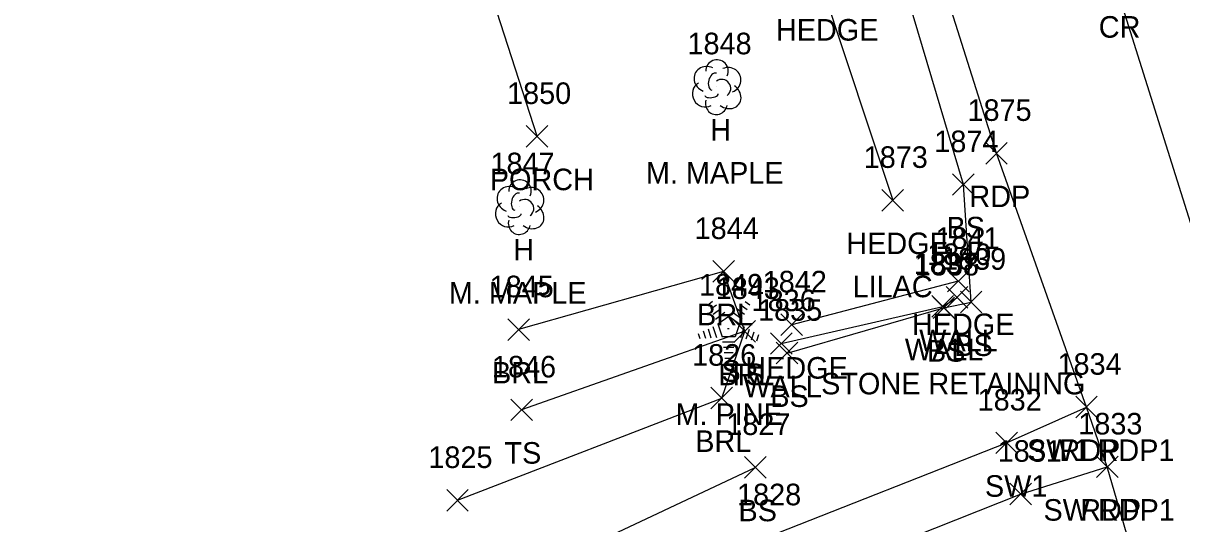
# Model space of a CAD drawing. Extents: x 1620157 to 1620595, y 115111 to 117885.
# Drawn here: x 1620193.4 to 1620300.9, y 115501.6 to 115548.1 of the extents above; entities that cross this region are included whole.
import ezdxf

# ---------------------------------------------------------------- set-up
doc = ezdxf.new("R2010")
doc.units = 0
for name, color, linetype in [('L_A', 7, 'Continuous'), ('L_C', 7, 'Continuous'), ('L_I', 7, 'Continuous'), ('L_TIC', 7, 'Continuous'), ('LABL', 7, 'Continuous'), ('LAHR', 7, 'Continuous'), ('LBF', 7, 'Continuous'), ('LELB', 7, 'Continuous'), ('LTC', 7, 'Continuous'), ('LTD', 7, 'Continuous'), ('LW', 7, 'Continuous'), ('P_A', 7, 'Continuous'), ('P_I', 7, 'Continuous'), ('P_TIC', 7, 'Continuous'), ('PET', 7, 'Continuous'), ('PRC', 7, 'Continuous'), ('R_A', 7, 'Continuous'), ('R_I', 7, 'Continuous'), ('R_TIC', 7, 'Continuous'), ('RSW', 7, 'Continuous')]:
    doc.layers.add(name, color=color, linetype=linetype)

msp = doc.modelspace()

# ---------------------------------------------------------------- linework, layer by layer
at = {"layer": 'L_TIC'}
for points in [[(1620240.04, 115536.59), (1620242.04, 115538.59)], [(1620242.04, 115536.59), (1620240.04, 115538.59)], [(1620279.6, 115532.12), (1620281.6, 115534.12)], [(1620281.6, 115532.12), (1620279.6, 115534.12)], [(1620273.04, 115530.66), (1620275.04, 115532.66)], [(1620275.04, 115530.66), (1620273.04, 115532.66)], [(1620257.35, 115524.06), (1620259.35, 115526.06)], [(1620259.35, 115524.06), (1620257.35, 115526.06)], [(1620279.13, 115523.15), (1620281.13, 115525.15)], [(1620281.13, 115523.15), (1620279.13, 115525.15)], [(1620279.01, 115521.65), (1620281.01, 115523.65)], [(1620281.01, 115521.65), (1620279.01, 115523.65)], [(1620280.32, 115521.21), (1620282.32, 115523.21)], [(1620282.32, 115521.21), (1620280.32, 115523.21)], [(1620277.68, 115520.81), (1620279.68, 115522.81)], [(1620279.68, 115520.81), (1620277.68, 115522.81)], [(1620277.78, 115520.68), (1620279.78, 115522.68)], [(1620279.78, 115520.68), (1620277.78, 115522.68)], [(1620263.67, 115519.11), (1620265.67, 115521.11)], [(1620265.67, 115519.11), (1620263.67, 115521.11)], [(1620238.33, 115518.66), (1620240.33, 115520.66)], [(1620240.33, 115518.66), (1620238.33, 115520.66)], [(1620259.32, 115518.5), (1620261.32, 115520.5)], [(1620261.32, 115518.5), (1620259.32, 115520.5)], [(1620259.32, 115518.5), (1620261.32, 115520.5)], [(1620261.32, 115518.5), (1620259.32, 115520.5)], [(1620262.7, 115517.37), (1620264.7, 115519.37)], [(1620264.7, 115517.37), (1620262.7, 115519.37)], [(1620263.24, 115516.48), (1620265.24, 115518.48)], [(1620265.24, 115516.48), (1620263.24, 115518.48)], [(1620257.18, 115512.31), (1620259.18, 115514.31)], [(1620259.18, 115512.31), (1620257.18, 115514.31)], [(1620238.61, 115511.22), (1620240.61, 115513.22)], [(1620240.61, 115511.22), (1620238.61, 115513.22)], [(1620260.29, 115505.88), (1620262.29, 115507.88)], [(1620262.29, 115505.88), (1620260.29, 115507.88)], [(1620232.66, 115502.82), (1620234.66, 115504.82)], [(1620234.66, 115502.82), (1620232.66, 115504.82)]]:
    msp.add_lwpolyline(points, dxfattribs=at)
at = {"layer": 'LABL'}
msp.add_lwpolyline([(1620233.66, 115503.82), (1620258.18, 115513.31), (1620260.32, 115519.5), (1620258.35, 115525.06), (1620239.33, 115519.66)], dxfattribs=at)
at = {"layer": 'LAHR'}
for points in [[(1620267.51, 115551.47), (1620274.04, 115531.66)], [(1620280.13, 115524.15), (1620264.67, 115520.11)]]:
    msp.add_lwpolyline(points, dxfattribs=at)
at = {"layer": 'LBF'}
msp.add_lwpolyline([(1620241.04, 115537.59), (1620235.29, 115555.41), (1620233.08, 115561.87), (1620232.99, 115562.77)], dxfattribs=at)
at = {"layer": 'LELB'}
for points in [[(1620264.24, 115517.48), (1620278.78, 115521.68), (1620281.32, 115522.21), (1620280.6, 115533.12), (1620271.27, 115564.52), (1620264.78, 115582.86), (1620240.11, 115585.85)], [(1620260.32, 115519.5), (1620239.61, 115512.22)], [(1620235.85, 115494.91), (1620261.29, 115506.88)]]:
    msp.add_lwpolyline(points, dxfattribs=at)
at = {"layer": 'LTC'}
for p, q in [((1620256.97, 115522.03), (1620257.32, 115522.29)), ((1620257.18, 115521.57), (1620257.7, 115521.95)), ((1620259.99, 115521.92), (1620260.54, 115521.52)), ((1620260.36, 115522.27), (1620260.78, 115521.97)), ((1620257.39, 115521.1), (1620258.09, 115521.61)), ((1620257.59, 115520.63), (1620258.47, 115521.27)), ((1620257.82, 115520.18), (1620258.83, 115520.91)), ((1620258.83, 115520.91), (1620259.83, 115520.19)), ((1620259.25, 115521.23), (1620260.06, 115520.64)), ((1620259.62, 115521.57), (1620260.3, 115521.08)), ((1620257.36, 115519.96), (1620257.7, 115518.94)), ((1620257.82, 115520.18), (1620258.21, 115518.99)), ((1620259.83, 115520.19), (1620259.44, 115518.99)), ((1620260.27, 115519.92), (1620259.93, 115518.88)), ((1620256, 115519.31), (1620256.15, 115518.84)), ((1620256.45, 115519.53), (1620256.67, 115518.87)), ((1620256.91, 115519.74), (1620257.18, 115518.91)), ((1620259.44, 115518.99), (1620258.21, 115518.99)), ((1620260.71, 115519.67), (1620260.42, 115518.78)), ((1620261.15, 115519.42), (1620260.92, 115518.69)), ((1620261.6, 115519.17), (1620261.41, 115518.59)), ((1620259.4, 115518.49), (1620258.25, 115518.49)), ((1620259.31, 115517.99), (1620258.33, 115517.99)), ((1620259.23, 115517.49), (1620258.4, 115517.49)), ((1620259.15, 115516.99), (1620258.47, 115516.99))]:
    msp.add_line(p, q, dxfattribs=at)
at = {"layer": 'LTD'}
for p, q in [((1620257.69, 115542.2), (1620257.69, 115542.2)), ((1620257.69, 115542.2), (1620257.69, 115542.2)), ((1620239.41, 115531.07), (1620239.41, 115531.07)), ((1620239.41, 115531.07), (1620239.41, 115531.07))]:
    msp.add_line(p, q, dxfattribs=at)
for centre in [(1620257.74, 115543.64), (1620239.46, 115532.5)]:
    msp.add_arc(centre, 1.05, 335.5272, 180.9563, dxfattribs=at)
for centre, major_axis, ratio, start_param, end_param in [((1620256.9, 115542.87), (1.21, -0.51), 0.895232, 1.570796, 4.712389), ((1620257.48, 115542.66), (-0.208, -0.792), 0.645439, 3.141593, 6.283185), ((1620258.73, 115542.79), (-1.14, -0.48), 0.949671, 1.570796, 4.712389), ((1620256.61, 115541.49), (0.58, -1.04), 0.959034, 3.141593, 6.283185), ((1620258.19, 115542.04), (-0.5, 0.667), 0.989748, 3.141593, 6.283185), ((1620257.23, 115541.45), (-0.625, -0.083), 0.423636, 0, 3.141593), ((1620258.69, 115541.37), (-1.09, 0.79), 0.841452, 1.570796, 4.712389), ((1620257.69, 115540.7), (0.26, 1.06), 0.942809, 1.570796, 4.712389), ((1620238.62, 115531.73), (1.21, -0.51), 0.895232, 1.570796, 4.712389), ((1620240.45, 115531.65), (-1.14, -0.48), 0.949671, 1.570796, 4.712389), ((1620239.2, 115531.52), (-0.208, -0.792), 0.645439, 3.141593, 6.283185), ((1620239.91, 115530.9), (-0.5, 0.667), 0.989748, 3.141593, 6.283185), ((1620238.33, 115530.36), (0.58, -1.04), 0.959034, 3.141593, 6.283185), ((1620240.41, 115530.23), (-1.09, 0.79), 0.841452, 1.570796, 4.712389), ((1620239.41, 115529.57), (0.26, 1.06), 0.942809, 1.570796, 4.712389), ((1620238.95, 115530.32), (-0.625, -0.083), 0.423636, 0, 3.141593)]:
    msp.add_ellipse(centre, major_axis=major_axis, ratio=ratio, start_param=start_param, end_param=end_param, dxfattribs=at)
at = {"layer": 'LW'}
msp.add_lwpolyline([(1620263.7, 115518.37), (1620278.68, 115521.81), (1620280.01, 115522.65)], dxfattribs=at)
at = {"layer": 'P_TIC'}
for points in [[(1620282.67, 115535.02), (1620284.67, 115537.02)], [(1620284.67, 115535.02), (1620282.67, 115537.02)], [(1620291.02, 115511.47), (1620293.02, 115513.47)], [(1620293.02, 115511.47), (1620291.02, 115513.47)], [(1620292.95, 115505.93), (1620294.95, 115507.93)], [(1620294.95, 115505.93), (1620292.95, 115507.93)]]:
    msp.add_lwpolyline(points, dxfattribs=at)
at = {"layer": 'PET'}
msp.add_lwpolyline([(1620320.14, 115439.39), (1620314.87, 115455.06), (1620309.06, 115464.39), (1620304.22, 115479.4), (1620297.09, 115496.09), (1620293.95, 115506.93), (1620292.02, 115512.47), (1620283.67, 115536.02), (1620274.58, 115564.81), (1620268.48, 115584.52), (1620253.11, 115635.23), (1620250.12, 115643.88), (1620242.65, 115668.01), (1620237.66, 115684.19), (1620235.08, 115693.76), (1620231.19, 115707.41), (1620225.41, 115727.43), (1620211.93, 115771.95), (1620203.83, 115799.04), (1620193.37, 115837.22)], dxfattribs=at)
at = {"layer": 'PRC'}
msp.add_lwpolyline([(1620328.08, 115447.46), (1620322.14, 115466.61), (1620311.32, 115499.81), (1620303.78, 115522.91), (1620294.72, 115551.74), (1620279.31, 115600.23), (1620271.12, 115626.45), (1620257.91, 115669.49), (1620247.64, 115703.03), (1620242.45, 115719.65), (1620232.98, 115752.35), (1620223.66, 115784.04), (1620214.14, 115816.15), (1620207.47, 115841.18)], dxfattribs=at)
at = {"layer": 'R_TIC'}
for points in [[(1620291.02, 115511.47), (1620293.02, 115513.47)], [(1620293.02, 115511.47), (1620291.02, 115513.47)], [(1620283.61, 115508.15), (1620285.61, 115510.15)], [(1620285.61, 115508.15), (1620283.61, 115510.15)], [(1620292.95, 115505.93), (1620294.95, 115507.93)], [(1620294.95, 115505.93), (1620292.95, 115507.93)], [(1620284.91, 115503.4), (1620286.91, 115505.4)], [(1620286.91, 115503.4), (1620284.91, 115505.4)]]:
    msp.add_lwpolyline(points, dxfattribs=at)
at = {"layer": 'RSW'}
for points in [[(1620234.45, 115488.01), (1620262.29, 115500.36), (1620284.61, 115509.15), (1620292.02, 115512.47)], [(1620236.4, 115483.58), (1620264.17, 115495.77), (1620285.91, 115504.4), (1620293.95, 115506.93)]]:
    msp.add_lwpolyline(points, dxfattribs=at)

# ---------------------------------------------------------------- texts
at = {"layer": 'L_A'}
for s, p in [('HEDGE', (1620263.21, 115546.47)), ('H', (1620257.12, 115537.2)), ('PORCH', (1620236.66, 115532.59)), ('BS', (1620279.04, 115528.12)), ('HEDGE', (1620269.74, 115526.66)), ('H', (1620238.84, 115526.07)), ('BRL', (1620255.89, 115520.06)), ('HEDGE', (1620275.83, 115519.15)), ('WALL', (1620275.17, 115516.81)), ('WALL', (1620276.5, 115517.65)), ('BS', (1620277.22, 115516.68)), ('BS', (1620279.76, 115517.21)), ('BRL', (1620236.87, 115514.66)), ('S', (1620258.16, 115514.82)), ('HEDGE', (1620260.37, 115515.11)), ('BRL', (1620257.86, 115514.5)), ('TS', (1620258.73, 115514.5)), ('WALL', (1620260.18, 115513.37)), ('BS', (1620262.68, 115512.48)), ('BRL', (1620255.72, 115508.31)), ('TS', (1620238.02, 115507.22)), ('BS', (1620259.73, 115501.88))]:
    msp.add_text(s, height=2, dxfattribs=at).set_placement(p)
at = {"layer": 'L_C'}
for s, p in [('M. MAPLE', (1620251.14, 115533.2)), ('LILAC', (1620270.31, 115522.66)), ('M. MAPLE', (1620232.86, 115522.07)), ('STONE RETAINING', (1620267.4, 115513.65)), ('M. PINE', (1620253.89, 115510.82))]:
    msp.add_text(s, height=2, dxfattribs=at).set_placement(p)
at = {"layer": 'L_I'}
for s, p in [('1848', (1620255, 115545.2)), ('1850', (1620238.26, 115540.59)), ('1874', (1620277.9, 115536.12)), ('1847', (1620236.72, 115534.07)), ('1873', (1620271.35, 115534.66)), ('1844', (1620255.66, 115528.06)), ('1841', (1620278.01, 115527.15)), ('1840', (1620277.23, 115525.65)), ('1837', (1620275.99, 115524.81)), ('1838', (1620276.09, 115524.68)), ('1839', (1620278.62, 115525.21)), ('1845', (1620236.64, 115522.66)), ('1849', (1620256.07, 115522.82)), ('1843', (1620257.62, 115522.5)), ('1843', (1620257.62, 115522.5)), ('1842', (1620261.98, 115523.11)), ('1836', (1620260.95, 115521.37)), ('1835', (1620261.55, 115520.48)), ('1826', (1620255.43, 115516.31)), ('1846', (1620236.86, 115515.22)), ('1827', (1620258.6, 115509.88)), ('1825', (1620230.96, 115506.82))]:
    msp.add_text(s, height=2, dxfattribs=at).set_placement(p)
at = {"layer": 'LTC'}
msp.add_text('.', height=1.04, rotation=270, dxfattribs=at).set_placement((1620258.71, 115519.93))
at = {"layer": 'P_A'}
for s, p in [('CR', (1620293.16, 115546.74)), ('RDP', (1620281.16, 115531.02)), ('RDP', (1620289.51, 115507.47)), ('RDP', (1620291.44, 115501.93))]:
    msp.add_text(s, height=2, dxfattribs=at).set_placement(p)
at = {"layer": 'P_I'}
for s, p in [('1875', (1620280.98, 115539.02)), ('1834', (1620289.33, 115515.47)), ('1833', (1620291.26, 115509.93))]:
    msp.add_text(s, height=2, dxfattribs=at).set_placement(p)
at = {"layer": 'R_A'}
for s, p in [('SW1 RDP1', (1620286.51, 115507.47)), ('SW1', (1620282.6, 115504.15)), ('SW RDP1', (1620288.03, 115501.93))]:
    msp.add_text(s, height=2, dxfattribs=at).set_placement(p)
at = {"layer": 'R_I'}
for s, p in [('1834', (1620289.33, 115515.47)), ('1832', (1620281.92, 115512.15)), ('1833', (1620291.26, 115509.93)), ('1831', (1620283.78, 115507.4)), ('1828', (1620259.6, 115503.36))]:
    msp.add_text(s, height=2, dxfattribs=at).set_placement(p)

doc.saveas('drawing.dxf')
